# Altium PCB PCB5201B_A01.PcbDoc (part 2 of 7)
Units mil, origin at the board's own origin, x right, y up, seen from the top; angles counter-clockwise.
Board outline 4527.56 x 2362.2 mil, 6 copper layers (Top Layer, GND Layer 2, Signal Layer 3, Signal Layer 4, VCC Layer 5, Bottom Layer), stack 61.221 mil thick; 361 components, 250 nets, 1223 pads, 1068 vias.
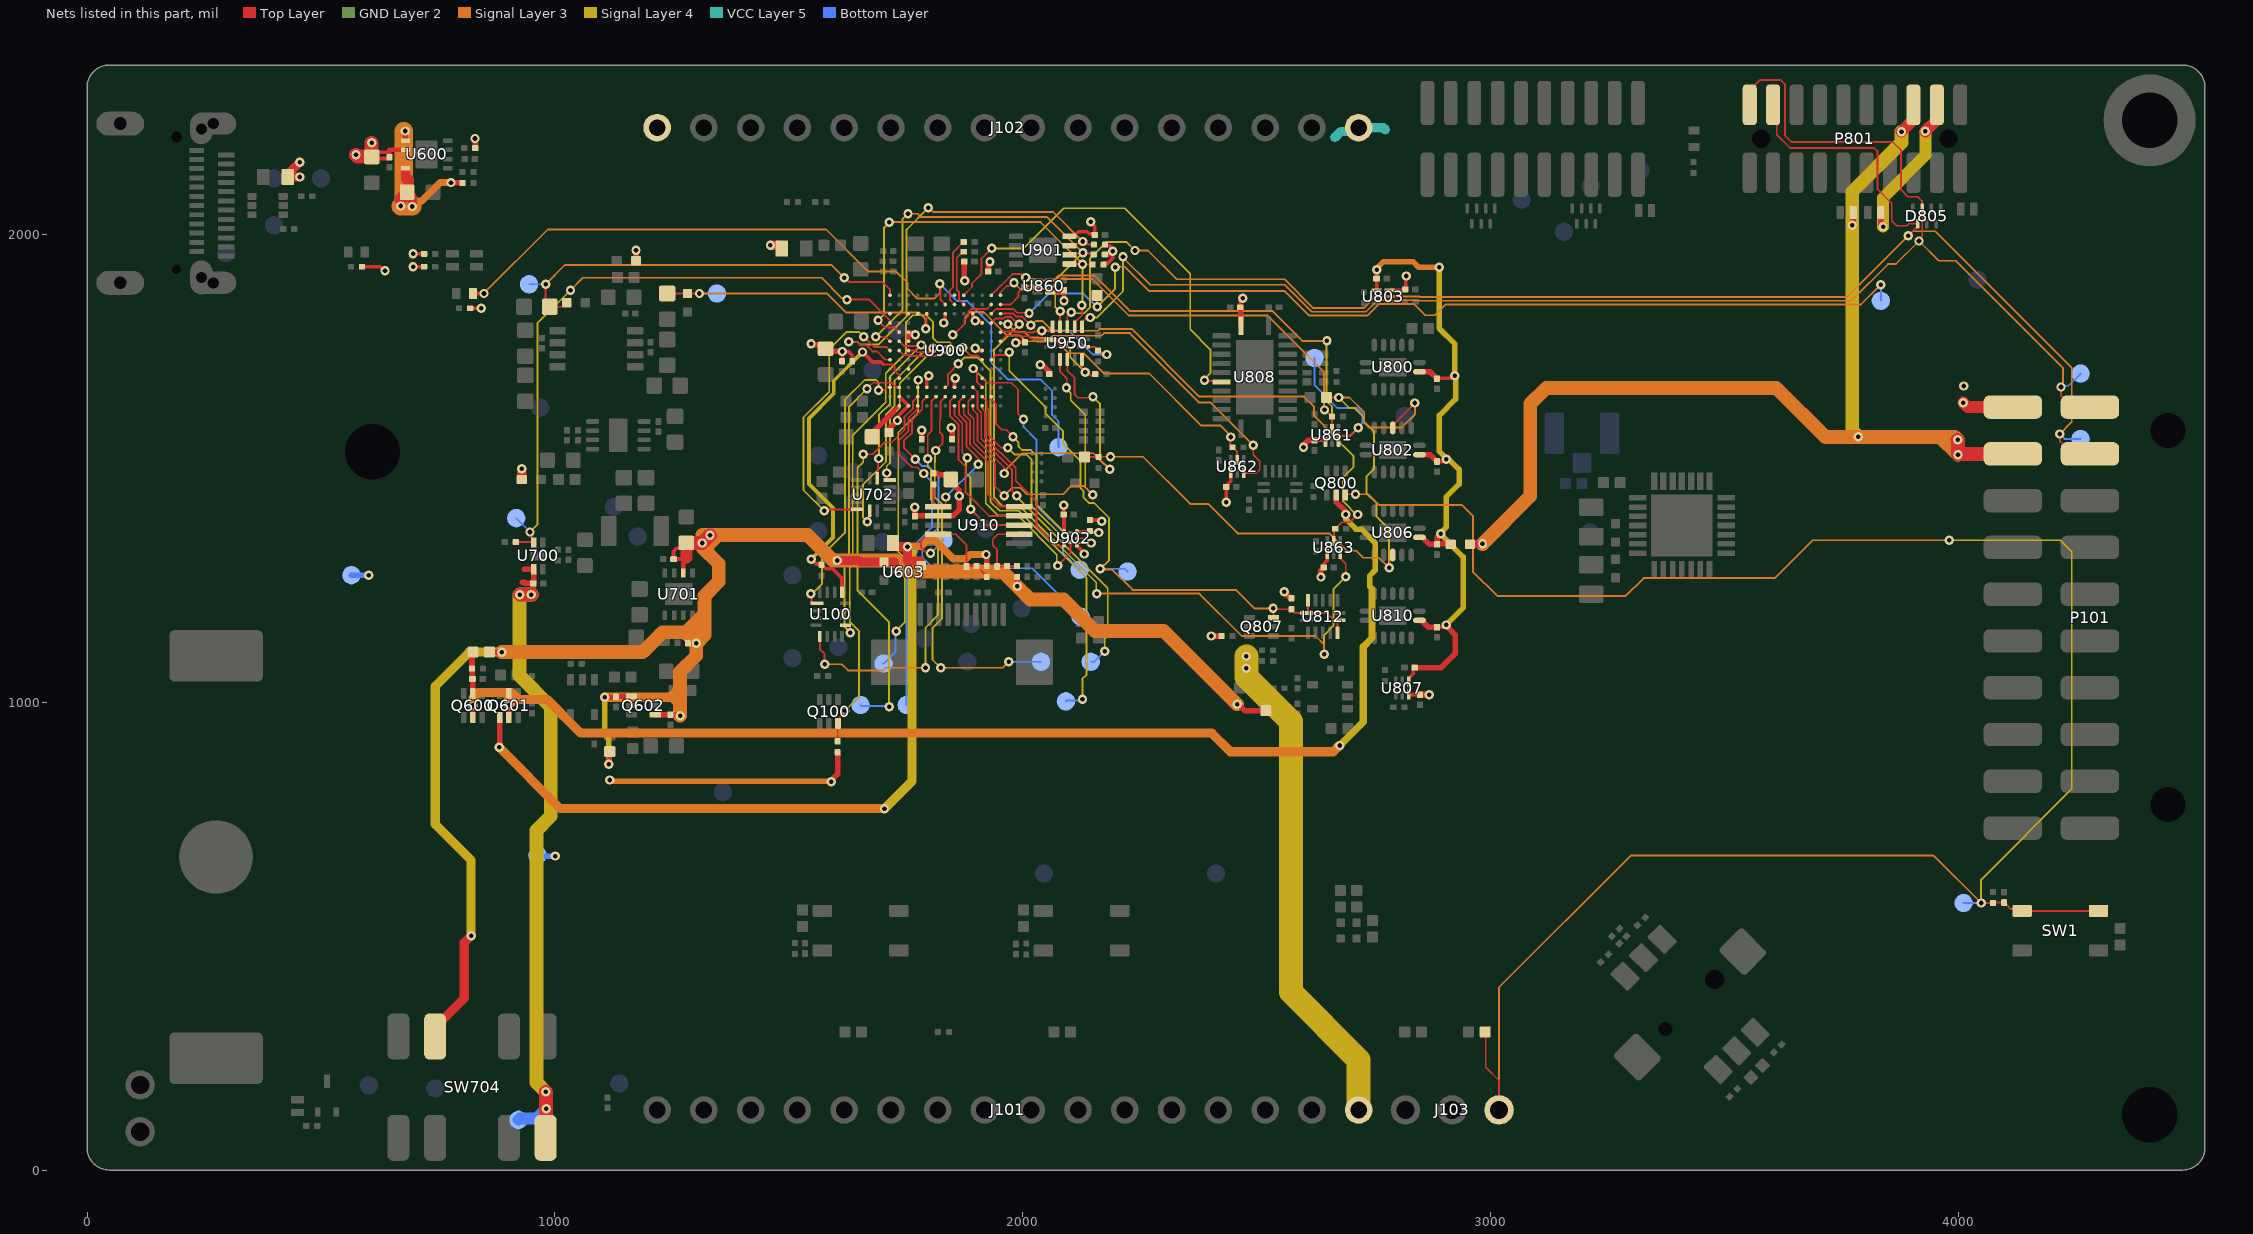
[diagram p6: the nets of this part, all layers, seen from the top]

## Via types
v1: diameter 20, hole 9.84, Top Layer to Bottom Layer, tented both sides, 1068 vias

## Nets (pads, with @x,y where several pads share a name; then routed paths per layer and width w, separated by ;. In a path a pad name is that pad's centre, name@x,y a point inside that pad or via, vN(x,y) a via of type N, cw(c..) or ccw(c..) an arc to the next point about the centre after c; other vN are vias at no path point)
3V3: C607.1 C807.1 C808.1 C860.1 C862.1 C864.1 C866.1 C868.1 C907.1 C908.1 C909.1 C910.1 C911.1 C914.1 C921.1 C922.1 C924.1 C925.1 C926.1 C927.1 C951.1 D807.1 J101.16 J102.16 L704.1 L900.1 P101.20 P801.3 R142.2 R601.2 R838.2 R840.2 R903.1 R906.2 R907.1 R908.1 R909.1 R912.1 R919.1 R920.1 R982.1 TPJ600.1 TPJ950.1 U600.1 U600.4 U803.6 U807.6 U808.1 U860.1 U861.1 U862.1 U863.1 U900.C6 U900.C9 U900.G3 U900.H11 U900.J11 U900.K3 U900.L4 U900.L7 U901.8 U902.A1 U902.E3 U910.2 | length 4365.6
  Top Layer w7.87: R903.1@587.6,1931.1 626.14,1931.1 634.99,1922.24 v1(636.81,1922.24) ; U600.1@680.4,2200.69 680.4,2206.59 ; v1(696.85,1931.1) R919.1@720.47,1931.1 ; v1(696.85,1958.66) R920.1@720.47,1958.66 ; R912.1@818.9,1842.52 v1(842.52,1842.52) ; C924.1@1614.17,1729.33 1614.17,1745.08 1619.09,1750 1627.95,1750 1635.83,1742.13 C925.1@1635.83,1729.33 ; U900.H11@1755.91,1771.65 U900.J11@1755.91,1791.34 1763.78,1791.34 1769.38,1785.74 v1(1770.64,1785.74) ; U900.C9@1795.28,1673.23 1795.28,1693.9 v1(1799.21,1697.83) ; v1(1831.69,1811.02) 1832.68,1811.02 1834.65,1812.99 U900.L7@1834.65,1830.71 ; U900.C6@1854.33,1673.23 1854.33,1689.96 v1@1857.28,1692.91 ; U900.L4@1893.7,1830.71 1893.7,1824.8 1899.61,1818.9 1899.61,1816.93 v1(1898.62,1815.94) 1908.47,1815.94 U900.K3@1913.39,1811.02 ; v1(1898.62,1756.89) 1903.54,1751.97 U900.G3@1913.39,1751.97 ; v1(1985.24,1768.7) 1986.22,1769.69 C911.1@2004.92,1769.69 ; U860.1@2059.06,1875.98 2083.66,1875.98 C862.1@2088.58,1880.91 2088.58,1858.43 v1(2088.48,1858.33) ; v1@2082.68,1421.26 2087.6,1416.34 C914.1@2087.6,1401.57 2088.58,1400.59 U902.A1@2088.58,1366.14 ; U901.8@2105.32,1996.06 2109.04,1996.06 2118.88,2005.91 2137.8,2005.91 2142.19,2001.51 2152.06,2001.51 C951.1@2154.42,1999.15 2154.42,2017.26 2147.64,2024.04 v1@2147.64,2025 ; U902.E3@2116.14,1334.65 2116.14,1334.54 2131.71,1318.97 v1(2131.71,1317.11) ; R906.2@2143.7,1389.76 2166.34,1389.76 v1(2169.29,1386.81) ; v1(2145.59,2027.65) 2145.59,2027.05 v1@2147.64,2025 ; v1@2147.64,2026.57 v1@2147.64,2025 ; v1@2150.59,2022.05 v1@2147.64,2025 ; R908.1@2170.84,1936.02 2172.92,1938.11 2181.22,1938.11 2192.75,1949.64 2192.75,1964.4 v1(2192.91,1964.57) ; R909.1@2175.2,1977.36 2176.55,1976.01 2186.24,1976.01 2193.9,1968.35 v1@2193.9,1964.57 ; v1(2435.67,1427.3) 2435.35,1427.62 2435.35,1460.32 C860.1@2435.04,1460.63 2435.04,1462.6 2444.88,1472.44 U862.1@2444.88,1490.16 ; C808.1@2465.55,1844.49 2465.55,1859.25 v1(2470.47,1864.17) ; C864.1@2624.02,1560.04 2644.69,1560.04 U861.1@2647.64,1557.09 ; C866.1@2643.7,1288.39 2643.7,1296.26 2651.58,1304.13 U863.1@2651.58,1316.93 ; U803.6@2784.45,1880.91 2814.76,1880.91 2814.96,1881.1 C807.1@2814.96,1882.87 ; C807.1@2817.91,1882.87 2818.9,1883.86 2818.9,1910.43 v1(2819.88,1911.42) ; U807.6@2825.31,1016.73 2825.31,1016.52 2847.22,1016.52 C868.1@2847.44,1016.73
  Top Layer w9.84: 680.4,2135.73 U600.4@680.4,2141.63
  Top Layer w11.81: 680.4,2206.59 v1(680.4,2221.36) ; v1(777.84,2111.12) 778.34,2110.63 802.06,2110.63 R601.2@802.45,2110.14 R601.2@802.45,2110.14 ; v1(1547.73,1766.35) 1549.3,1764.78 1569.86,1764.78 1584.65,1750 v1(1614.17,1750) v1@1619.09,1750 ; v1(1590.55,830.1) 1590.55,832.32 1604.57,846.34 R142.2@1604.57,893.02 ; v1(1769.69,1417.32) C922.1@1769.69,1397.64 1770.67,1398.62 U910.2@1819.88,1398.62 1851.38,1398.62 1864.17,1411.42 1864.17,1453.74 C921.1@1843.5,1474.41 ; C927.1@1784.45,1562.01 v1(1784.45,1581.69) ; R982.1@1809.2,1489.42 1809.2,1489.03 1809.59,1488.64 1818.45,1488.64 1820.87,1486.22 1836.61,1486.22 C921.1@1846.46,1476.38 ; v1(1847.44,1586.61) 1849.41,1584.65 C926.1@1849.41,1562.01 ; v1@1875.35,1902.21 C910.1@1875.35,1942.24 ; C908.1@1926.18,1921.26 1926.18,1937.99 v1(1930.12,1941.93) ; v1(2037.32,1721.98) 2038.89,1720.42 2043.33,1720.42 2056.09,1707.66 2056.09,1702.14 2056.48,1701.75 C909.1@2057.27,1701.75 ; R907.1@2175.77,1957.7 2176.17,1958.1 2184.23,1958.1 2189.13,1963 v1@2191.53,1963 ; v1(2403.54,1141.73) 2403.62,1141.66 2425.17,1141.66 R838.2@2425.24,1141.59 ; C808.1@2465.55,1844.49 2466.54,1843.5 U808.1@2466.54,1804.92 ; v1(2559.06,1236.22) 2572.83,1222.44 R840.2@2574.8,1222.44 ; v1(2600.39,1545.28) 2600.39,1550.2 2610.24,1560.04 C864.1@2624.02,1560.04 ; v1(2637.8,1267.72) 2637.8,1282.48 C866.1@2643.7,1288.39 ; D807.1@3834.65,2047.24 3834.65,2021.65 v1(3839.57,2016.73) ; L704.1@1173.5,1943.9 v1(1173.5,1966.54) L704.1@1173.5,1943.9
  Top Layer w13.78: C868.1@2849.45,1016.3 2849.65,1016.1 2868.74,1016.1 v1(2869.09,1015.75)
  Top Layer w19.68: v1(670.56,2060.92) 670.62,2060.98 C607.1@670.62,2075.75 ; 680.4,2118.11 680.4,2135.73 ; C607.1@684.34,2089.47 C607.1@684.34,2090.45 ; 688.98,2118.11 688.98,2095.09 C607.1@684.34,2090.45 ; v1(695.17,2059.94) 695.17,2079.63 C607.1@684.34,2090.45 ; v1(1460.86,1977.05) 1460.92,1976.99 1480.91,1976.99 L900.1@1488.75,1969.14
  Top Layer w25: v1(3930.12,2220.47) 3954.53,2244.88 P801.3@3954.53,2277.22 ; v1(4010.83,1640.75) 4020.47,1631.1 P101.20@4116.93,1631.1
  Top Layer w27.56: C607.1@670.62,2075.75 C607.1@684.34,2089.47
  Signal Layer 3 w11.81: 679.13,2095.47 702.76,2071.85 ; v1(695.17,2059.94) 696.73,2061.51 705.21,2061.51 715.55,2071.85 ; v1(1116.99,833.91) 1118.56,832.34 1124.35,832.34 1125.02,831.67 v1@1588.56,831.67
  Signal Layer 3 w15.75: 702.76,2071.85 715.55,2071.85 754.82,2111.12 v1(777.84,2111.12)
  Signal Layer 3 w39.37: v1@670.47,2060.83 671.36,2059.94 v1(695.17,2059.94) ; 676.83,2078.28 v1@676.83,2221.36
  Signal Layer 4 w25: v1(3839.57,2016.73) 3839.57,2078.74 3930.12,2169.29 v1(3930.12,2220.47)
  Signal Layer 4 w51.18: v1(2478.35,1098.43) v1(2478.35,1072.83) 2478.35,1054.13 2573.82,958.66 2573.82,380.24 2718.5,235.55 J101.16@2718.5,128.43
  VCC Layer 5 w20: 2667.68,2207.72 2680.16,2220.2 2710.28,2220.2 J102.16@2718.5,2228.43 ; J102.16@2711.69,2228.43 J102.16@2718.5,2228.43 ; 2775.59,2224.41 2771.57,2228.43 J102.16@2718.5,2228.43
  Bottom Layer w11.81: TPJ600.1@565.09,1271.73 v1(602.36,1271.65) ; TPJ950.1@962.69,673.23 964.66,671.26 v1(1000.98,671.26)
  other v1: 2087.6,1421.26 1864.17,1440.94 4011.81,1676.18 1856.3,1692.91 1875.98,1901.57
3V6_SW: C608.1 L702.1 Q601.1 R639.2 U603.B1 | length 1860.8
  Top Layer w7.87: U603.B1@1753.94,1285.43 1753.94,1302.17
  Top Layer w11.81: v1@881.89,903.54 Q601.1@881.89,967.52 ; v1(1921.84,1316.04) 1922.84,1315.04 1922.84,1291.73 R639.2@1923.23,1291.34
  Top Layer w19.68: L702.1@1723.03,1340.55 1730.91,1332.68 v1(1753.94,1332.68) 1753.94,1302.17 1780.51,1302.17 C608.1@1783.47,1299.21
  Signal Layer 3 w15.75: v1(1753.94,1332.68) 1754.75,1333.49 1783.45,1333.49 1795.43,1345.47 1812.99,1345.47 1851.38,1307.09 1878.94,1307.09 1887.89,1316.04 v1(1921.84,1316.04)
  Signal Layer 3 w19.68: v1(880.91,903.54) 1011.81,772.64 v1(1704.72,772.64)
  Signal Layer 4 w19.68: v1(1704.72,772.64) 1763.78,831.69 1763.78,1322.75 1753.94,1332.59 v1(1753.94,1332.68)
3V6_SW_SENSE: C641.1 R639.1 R640.2 TP923.1 U910.4 | length 292.7
  Top Layer w3.94: v1(1803.15,1318.9) 1795.28,1318.9 1782.48,1331.69 1782.48,1346.46 1795.28,1359.25 U910.4@1819.88,1359.25 1857.28,1359.25 1879.92,1336.61 C641.1@1879.92,1290.35 1880.91,1291.34 R640.2@1901.58,1291.34 1923.23,1269.69 R639.1@1923.23,1267.72
  Bottom Layer w3.94: v1(1803.15,1318.9) TP923.1@1830.71,1346.46
5V: C600.1 C609.1 C611.1 C673.1 C674.1 C702.1 C703.1 C901.1 D806.1 J102.1 L600.2 L700.1 L800.1 P101.18 P801.5 Q602.1 Q602.4 R600.2 R622.2 R633.2 R681.2 R690.2 R700.2 SW704.3 U600.2 U603.A2 U603.B2 U701.2 U900.A11 U900.B12 | length 7093.1
  Top Layer w7.87: C611.1@608.37,2166.32 cw(c612.04,2159.35) C611.1@613.86,2167.01 ; 646.33,2181 646.33,2176.18 ; C702.1@1253.74,1308.32 1253.74,1322.64 1260.29,1329.19 1272.1,1329.19 C703.1@1275.59,1332.68 ; C702.1@1254.27,1306.48 1279.98,1306.48 1278.54,1302.17 1274.61,1298.23 ; R700.2@1284.51,1126.43 1284.73,1126.21 1301.94,1126.21 v1(1302.17,1125.98) ; 1726.38,1300.2 1738.19,1288.39 U603.B2@1738.19,1285.43 1733.27,1285.43 1728.35,1280.51 1728.35,1274.61 1733.27,1269.69 U603.A2@1738.19,1269.69 ; v1(1732.37,1602.43) 1732.37,1610.32 U900.A11@1755.91,1633.86 U900.B12@1736.22,1653.54 ; 646.33,2176.18 646.33,2164.76 643.97,2162.4 612.37,2162.4 C611.1@608.85,2165.92 619.11,2176.18 646.33,2176.18
  Top Layer w9.84: 646.33,2181 U600.2@680.4,2181 ; U701.2@1274.61,1276.57 1274.61,1298.23
  Top Layer w11.81: v1(820.87,500.98) v1@820.93,500.92 ; v1(829.19,2205.4) 829.6,2204.99 829.6,2185.33 R600.2@829.99,2184.94 ; R622.2@860.24,1107.28 v1(886.81,1107.28) ; v1(1106.3,1010.83) 1106.72,1011.25 1130.03,1011.25 C674.1@1130.42,1011.67 ; v1(1115.55,867.81) 1116.43,868.7 1116.43,893.67 R681.2@1117.32,894.55 ; C674.1@1130.42,1011.67 1130.42,1012.4 1130.82,1012.8 Q602.1@1163.39,1012.8 ; Q602.4@1214.57,973.43 C673.1@1247.05,973.43 ; C673.1@1247.05,973.27 1247.44,972.88 1263.97,972.88 1265.55,971.3 v1(1267.77,971.3) ; C901.1@1714.57,1576.77 1714.57,1584.63 v1(1732.37,1602.43) ; v1(1988.19,1248.03) R633.2@1988.19,1267.72 ; v1(2458.53,995.84) 2460.74,995.84 2474.53,982.05 R690.2@2520.52,982.05 ; v1(3773.62,2019.69) 3775.59,2021.65 D806.1@3775.59,2047.24
  Top Layer w15.75: L800.1@2956.66,1337.73 2982.42,1337.73 v1(2983.27,1338.58)
  Top Layer w19.68: L600.2@429.15,2123.09 v1@454.7,2123.06 ; L600.2@429.15,2123.09 432.49,2126.43 432.49,2132.14 v1(454.75,2154.4) ; SW704.3@744.09,285.43 744.09,309.96 757.72,323.59 762.56,323.59 806.1,367.13 806.1,486.22 v1@819.88,500 ; L700.1@929.13,1476.38 v1(929.13,1499.02) ; v1(1603.92,1303.15) 1650.34,1303.15 1653.29,1300.2 C609.1@1703.74,1300.2 1726.38,1300.2
  Top Layer w25: v1(3878.94,2219.49) 3904.53,2245.08 P801.5@3904.53,2277.22
  Top Layer w25.59: 1281.5,1309.06 C703.1@1281.5,1340.43
  Top Layer w29.53: v1(574.8,2170.28) 578.17,2166.91 607.87,2166.91 C611.1@608.27,2166.51 ; v1(608.27,2195.87) C611.1@608.27,2166.51 ; C611.1@608.85,2165.92 C611.1@608.27,2166.51 ; C703.1@1280.92,1341 C703.1@1281.37,1340.55 ; C703.1@1281.5,1340.43 C703.1@1281.37,1340.55 ; v1(1331.69,1357.28) v1(1314.96,1340.55) C703.1@1281.37,1340.55 ; v1@3998.03,1561.02 3999.79,1559.26 v1(3999.79,1529.15) 4001.75,1531.1 P101.18@4116.93,1531.1
  Signal Layer 3 w19.68: v1(1106.3,1010.83) 1246.06,1010.83 ; 1262.8,1029.53 1262.8,1027.56 1246.06,1010.83 ; 1266.73,994.09 1250,1010.83 ; 1267.77,1010.83 1250,1010.83 ; 1246.06,1010.83 1250,1010.83
  Signal Layer 3 w29.53: v1(886.81,1107.28) 1187.99,1107.28 1230.31,1149.61 1278.54,1149.61 ; v1(1267.77,971.3) 1267.77,1010.83 1267.77,1065.01 1302.17,1099.41 v1@1302.17,1123.03 ; 1318.9,1179.13 1318.9,1163.39 1291.83,1136.32 ; 1318.9,1187.99 1280.51,1149.61 1278.54,1149.61 ; v1(1331.69,1357.28) v1@1331.99,1357.58 ; 1361.22,1357.28 1348.43,1357.28 1322.83,1331.69 v1@1314.96,1331.69 ; v1(2458.53,995.84) 2427.55,1026.82 2301.81,1152.56 2154.53,1152.56 2087.32,1219.77 2016.45,1219.77 v1(1988.19,1248.03) 1956.69,1279.53 1752.95,1279.53 1729.33,1303.15 v1(1603.92,1303.15) 1594.49,1303.15 1540.05,1357.58 v1@1331.99,1357.58 ; v1(2983.27,1338.58) 3085.11,1440.43 3085.11,1637.88 3119.48,1672.24 3611.22,1672.24 3716.13,1567.34 3961.6,1567.34 ; v1@3994.09,1565.94 3992.7,1567.34 3961.6,1567.34 ; v1@3999.05,1534.48 v1(3999.05,1561.63) ; v1(3999.79,1529.15) 3961.6,1567.34 ; 1278.54,1149.61 1291.83,1136.32 ; 1291.83,1136.32 v1(1302.17,1125.98) 1302.58,1125.98 1319.88,1143.28 1319.88,1227.36 1350.39,1257.87 1350.39,1296.26 v1@1314.96,1331.69 ; v1@1314.96,1331.69 v1(1314.96,1340.55) 1314.96,1357.58 v1@1331.99,1357.58
  Signal Layer 4 w11.81: v1(1106.3,1010.83) 1106.3,931.1 1115.55,921.85 v1(1115.55,867.81)
  Signal Layer 4 w19.68: v1(820.87,500.98) 820.87,662.4 744.09,739.17 744.09,1034.45 816.93,1107.28 v1(886.81,1107.28)
  Signal Layer 4 w29.53: v1(3786.42,1567.91) 3773.62,1580.71 v1(3773.62,2019.69) 3773.62,2091.54 3878.94,2196.85 v1(3878.94,2219.49)
  other v1: 454.72,2123.03
5V_DH_SW: C803.1 C805.1 C809.1 C827.1 C869.1 C870.1 L800.2 U800.14 U802.14 U803.1 U806.14 U807.1 U810.14 | length 1570.4
  Top Layer w7.87: C869.1@2756.65,1905.63 2756.77,1905.75 2756.77,1924.8 v1(2756.89,1924.92) ; U803.1@2756.89,1880.91 2756.77,1880.91 2756.77,1903.43 C869.1@2756.89,1903.54 ; U807.1@2825.31,1044.29 2825.31,1051.18 2835,1060.87 2835,1071.81 2836.02,1072.83 C870.1@2837.6,1072.83 ; C827.1@2885.83,1160.43 2900.59,1160.43 v1(2905.51,1165.35) ; C805.1@2885.83,1514.76 2900.59,1514.76 v1(2905.51,1519.69) ; C803.1@2886.81,1692.91 2919.29,1692.91 v1(2924.21,1697.83)
  Top Layer w11.81: C870.1@2838.15,1074.17 2895.04,1074.17 2924.92,1104.05 2924.92,1143.98 2909.45,1159.45 v1@2909.45,1166.34 ; U810.14@2848.43,1175.2 2853.35,1175.2 2868.11,1160.43 C827.1@2885.83,1160.43 ; U806.14@2848.43,1352.36 2855.31,1352.36 2870.08,1337.6 C809.1@2885.83,1337.6 2886.22,1337.99 2886.22,1353.2 2893.3,1360.27 v1(2894.12,1360.27) ; U802.14@2848.43,1529.53 2871.06,1529.53 C805.1@2885.83,1514.76 ; U800.14@2848.43,1706.69 2871.06,1706.69 C803.1@2885.83,1691.93 C803.1@2886.81,1692.91 ; C809.1@2886.22,1338.58 2914.48,1338.58 L800.2@2915.33,1337.73
  Signal Layer 3 w11.81: v1(2756.89,1924.92) 2756.89,1927.13 2762.09,1932.33 2762.09,1932.96 2771.06,1941.93 2834.65,1941.93 2846.46,1930.12 v1(2890.75,1930.12)
  Signal Layer 4 w11.81: v1(2890.75,1930.12) 2890.75,1799.21 2924.21,1765.75 v1(2924.21,1697.83) 2925.78,1696.27 2925.78,1690.48 2925.9,1690.36 2925.9,1648.34 2891.03,1613.47 2891.03,1536.39 2905.51,1521.9 v1(2905.51,1519.69) ; v1(2905.51,1165.35) 2941.93,1201.77 2941.93,1311.02 2894.12,1358.83 2894.12,1362.49 2905.51,1373.88 2905.51,1438.98 2933.07,1466.54 2933.07,1498.03 v1@2908.46,1522.64
5V_SENSE: C635.1 R633.1 R634.2 U910.7 | length 166.9
  Top Layer w3.94: R633.1@1988.19,1291.34 R634.2@1966.54,1291.34 1965.55,1290.35 C635.1@1944.88,1290.35 1944.88,1326.77 1936.3,1335.35 1936.3,1348.93 1946.63,1359.25 U910.7@1993.11,1359.25
5V_SW: C610.1 Q600.2 Q600.5 Q601.2 Q601.5 Q800.5 R622.1 R623.2 | length 2790.4
  Top Layer w11.81: C610.1@823.82,1050.2 823.82,1070.87 R623.2@822.84,1071.85 822.84,1105.32 R622.1@824.8,1107.28 ; Q600.2@824.8,967.52 v1(824.8,993.11) 824.8,994.09 Q600.5@824.8,1018.7 C610.1@824.8,1049.21 ; Q601.2@901.58,967.52 v1(901.57,994.09) Q601.5@901.58,1018.7 ; Q800.5@2670.28,1442.91 2670.28,1428.15 2690.94,1407.48 v1(2690.94,1401.57)
  Signal Layer 3 w19.68: v1(824.8,993.11) 824.8,1008.89 836.59,1020.67 892.72,1020.67 901.57,1011.81 v1(901.57,994.09) 913.39,1005.91 923.23,1005.91 ; 894.68,1020.67 901.57,1020.67 908.46,1020.67 918.31,1010.83 923.23,1005.91 ; v1(2677.63,907.56) 2664.13,894.06 2444.52,894.06 2404.53,934.06 1055.12,934.06 983.27,1005.91 923.23,1005.91
  Signal Layer 4 w11.81: v1(2690.94,1401.57) 2690.94,1391.73 2712.6,1370.08 2724.41,1370.08 2753.94,1340.55 2753.94,1282.48 2741.85,1270.39 2741.85,1247.33 2747.05,1242.13
  Signal Layer 4 w15.75: v1(2677.63,907.56) 2728.63,958.56 2728.63,1119.09 2747.05,1137.51 2747.05,1242.13
#RESET: R805.2 R809.1 R810.2 U802.4 U806.11 | length 1546.8
  Top Layer w3.94: R810.2@2131.89,1524.61 R809.1@2162.4,1524.61 2162.89,1525.1 v1(2187.99,1525.1) ; R805.2@2649.61,1651.57 v1(2676.18,1651.57) ; v1(2783.46,1287.4) 2785.36,1289.3 2785.36,1300.12 2791.34,1306.1 U806.11@2791.34,1314.96 ; U802.4@2791.34,1586.61 2791.34,1592.52 v1(2838.58,1639.76)
  Signal Layer 3 w3.94: v1(2187.99,1525.1) 2257.38,1525.1 2358.27,1424.21 2396.65,1424.21 2459.65,1361.22 2655.51,1361.22 2692.63,1324.1 2713.3,1324.1 2728.35,1309.06 2761.81,1309.06 v1(2783.46,1287.4) ; v1(2676.18,1651.57) 2698.82,1651.57 2730.32,1620.08 2730.32,1597.44 2740.16,1587.6 2811.02,1587.6 2838.58,1615.16 v1(2838.58,1639.76)
  Signal Layer 4 w3.94: v1(2676.18,1651.57) 2698.82,1628.94 2709.65,1628.94 2729.33,1609.25 2729.33,1601.38 2750.98,1579.72 2750.98,1498.03 2734.96,1482 2734.96,1447.13 2756.89,1425.2 2756.89,1396.65 2783.46,1370.08 v1(2783.46,1287.4)
AEM_5V_#ENABLE: U900.L10
AEM_CALIBRATE0: U702.13 U900.G11 | length 527.1
  Top Layer w3.94: v1(1668.03,1386.34) 1668.03,1390.68 1671.26,1393.92 1671.26,1407.09 U702.13@1673.23,1409.06 ; U900.G11@1755.91,1751.97 1771.35,1751.97 1774.93,1748.39 1798.12,1748.39 1805.63,1755.91 v1@1809.06,1755.91
  Signal Layer 4 w3.94: v1(1668.03,1386.34) 1668.03,1386.45 1658.46,1396.01 1658.46,1465.11 1708.18,1514.82 1708.18,1615.66 1726.38,1633.86 1726.38,1687.99 1786.42,1748.03 1798.46,1748.03 1807.69,1757.26 v1(1808.46,1757.26)
AEM_CALIBRATE1: U702.5 U900.G12 | length 468.6
  Top Layer w3.94: v1(1709.65,1490.16) 1709.65,1477.36 1711.61,1475.39 U702.5@1715.95,1475.39 ; U900.G12@1736.22,1751.97 1746.06,1742.13 1759.98,1742.13 1761.88,1740.23 1823.89,1740.23 v1(1837.6,1753.94)
  GND Layer 2 w3.94: v1(1709.65,1490.16) v1@1711.95,1492.46
  Signal Layer 4 w3.94: v1(1709.65,1490.16) 1709.65,1505.15 1716.54,1512.04 1716.54,1609.25 1737.2,1629.92 1737.2,1682.09 1795,1739.88 1823.54,1739.88 v1(1837.6,1753.94)
AEM_CALIBRATE2: U702.6 U900.H12 | length 376.6
  Top Layer w3.94: U702.6@1688.98,1478.74 1690.84,1480.61 1690.84,1519.36 v1(1692.71,1521.23) ; U900.H12@1736.22,1771.65 1746.06,1761.81 1781.51,1761.81 v1(1783.56,1763.86)
  Signal Layer 4 w3.94: v1(1692.71,1521.23) 1692.71,1614.28 1716.54,1638.1 1716.54,1696.84 v1(1783.56,1763.86)
AEM_CALIBRATE3: U702.12 U900.G13 | length 619.7
  Top Layer w3.94: v1(1575.76,1409.42) 1578.74,1412.4 U702.12@1646.26,1412.4 ; v1(1660.43,1781.5) 1682.09,1759.84 1708.66,1759.84 U900.G13@1716.54,1751.97
  Signal Layer 4 w3.94: v1(1575.76,1409.42) 1575.76,1409.48 1531.5,1453.74 1531.5,1608.95 1586.61,1664.07 1586.61,1754.92 1623.03,1791.34 1650.59,1791.34 v1(1660.43,1781.5)
AEM_CURRENT_HIGH_GAIN: C720.1 R764.2 TP706.1 U900.N13 | length 914.6
  Top Layer w3.94: v1(980.31,1893.7) 980.31,1854.33 R764.2@989.17,1845.47 1016.73,1845.47 C720.1@1025.59,1854.33 ; v1(1618.78,1907.3) 1620.45,1907.3 1629.12,1898.62 1699.8,1898.62 1716.54,1881.89 U900.N13@1716.54,1870.08
  Signal Layer 3 w3.94: v1(980.31,1893.7) 1021.7,1935.08 1591,1935.08 v1(1618.78,1907.3)
  Bottom Layer w3.94: TP706.1@944.88,1893.7 v1(980.31,1893.7)
AEM_CURRENT_LOW_GAIN: C724.1 R768.2 TP707.1 U900.L9 | length 665.8
  Top Layer w3.94: R768.2@1240.16,1874.02 C724.1@1283.46,1874.02 v1(1309.06,1874.02) ; v1(1792.54,1798.7) 1794.52,1800.69 1794.52,1829.96 U900.L9@1795.28,1830.71
  Signal Layer 3 w3.94: v1(1309.06,1874.02) 1581.69,1874.02 1622.05,1833.66 1658.46,1833.66 1777.56,1833.66 1792.54,1818.68 v1(1792.54,1798.7)
  Bottom Layer w3.94: v1(1309.06,1874.02) TP707.1@1346.46,1874.02
AEM_SENSE_SELECT: U900.L13
AEM_SWITCH_POS: U900.L11
AEM_VMCU: C708.1 SW704.5 TP709.1 U700.1 | length 1505.4
  Top Layer w11.81: 930.12,1256.89 935.04,1256.89 937.01,1254.92 939.02,1254.92 939.61,1254.33 953.35,1254.33 C708.1@953.74,1253.94 ; 934.06,1284.45 U700.1@954.72,1284.45 954.72,1254.33 954.33,1253.94 C708.1@953.74,1253.94 ; v1(949.8,1230.32) 949.8,1232.53 953.74,1236.47 C708.1@953.74,1253.94
  Top Layer w29.53: v1(924.83,1229.91) 949.4,1229.91 v1(949.8,1230.32) ; SW704.5@980.32,68.9 981.3,69.88 981.3,166.34 v1(980.32,167.32)
  Signal Layer 4 w29.53: v1(949.8,1230.32) 947.83,1230.32 925.24,1230.32 v1(924.83,1229.91) 924.21,1229.29 924.21,1194.88 924.21,1057.09 991.14,990.16 991.14,756.54 960.63,726.03 960.63,187.01 v1(980.32,167.32) 980.32,131.89 v1(981.3,130.91)
  Bottom Layer w25: TP709.1@922.24,107.28 924.99,110.03 960.43,110.03 v1(981.3,130.91) 980.32,131.89 v1(980.32,167.32)
AEM_VMCU_ENABLE: R763.2 TP715.1 U700.4 U900.K13 | length 1396.3
  Top Layer w3.94: R763.2@916.5,1342.43 953.83,1342.43 U700.4@954.72,1341.54 954.72,1346.46 949.92,1351.26 949.92,1361.1 v1(946.85,1364.17) ; v1(1624.6,1860.9) 1672.43,1860.9 1716.4,1816.93 1716.4,1811.16 U900.K13@1716.54,1811.02
  Signal Layer 3 w3.94: v1(1033.46,1880.91) 1060.04,1907.48 1570.22,1907.48 1613.73,1863.97 1621.52,1863.97 v1(1624.6,1860.9)
  Signal Layer 4 w3.94: v1(946.85,1364.17) 962.6,1379.92 962.6,1810.04 v1(1033.46,1880.91)
  Bottom Layer w3.94: TP715.1@917.32,1393.7 v1(946.85,1364.17)
BC_ADC_SPI_CIPO: U900.B6 U910.9 | length 358.6
  Top Layer w3.94: U900.B6@1854.33,1653.54 1844.49,1643.7 1844.49,1612.26 1863.19,1593.56 1863.19,1518.7 1877.95,1503.94 1877.95,1448.82 1928.15,1398.62 U910.9@1993.11,1398.62
BC_ADC_SPI_COPI: U900.A6 U910.8 | length 348.3
  Top Layer w3.94: U900.A6@1854.33,1633.86 1854.33,1613.56 1871.06,1596.82 1871.06,1533.46 v1(1881.89,1522.64) ; v1(1888.78,1412.4) 1922.24,1378.94 U910.8@1993.11,1378.94
  Signal Layer 4 w3.94: v1@1878.94,1515.75 1878.94,1490.16 1888.78,1480.32 v1(1888.78,1412.4)
BC_ADC_SPI_CS: R982.2 U900.B5 U910.1 | length 352.1
  Top Layer w3.94: R982.2@1809.2,1465.8 1809.2,1422.24 1813.14,1418.31 U910.1@1819.88,1418.31 1831.69,1418.31 1835.63,1422.24 v1(1835.63,1438.98) ; U900.B5@1874.02,1653.54 1864.17,1643.7 1864.17,1614.85 1879.92,1599.1 1879.92,1547.24 1905.51,1521.65 v1(1905.51,1508.86)
  Bottom Layer w3.94: v1(1835.63,1438.98) 1901.57,1504.92 v1@1901.57,1507.87
BC_ADC_SPI_SCLK: U900.A5 U910.10 | length 289.1
  Top Layer w3.94: U900.A5@1874.02,1633.86 1874.02,1616.14 1887.8,1602.36 1887.8,1551.18 1926.18,1512.8 1926.18,1443.9 1951.77,1418.31 U910.10@1993.11,1418.31
BC_BUTTON_ENABLE: R981.1 U900.H1 U950.6 U950.12 | length 285.6
  Top Layer w3.94: U900.H1@1952.76,1771.65 1965.83,1784.73 1991.08,1784.73 1993.14,1782.68 2014.57,1782.68 2021.65,1775.59 U950.6@2060.63,1775.59 2087.55,1775.59 2098.58,1764.56 v1(2101.8,1764.56) ; U950.12@2126.97,1732.87 2126.97,1714.37 2133.86,1707.47 v1(2133.86,1705.56) ; v1@2134.79,1706.55 2134.85,1706.55 2136.99,1706.55 2145.19,1698.35 R981.1@2151.7,1698.35
  Signal Layer 4 w3.94: v1(2101.8,1764.56) 2101.8,1737.63 v1(2133.86,1705.56)
BC_DAC_OUT: U900.N6
BC_DBG_#RESET: LED903.1 TPJ956.1 U900.M7 | length 1704.8
  Top Layer w3.94: v1(1822.84,1894.69) 1824.8,1892.72 1824.8,1860.24 U900.M7@1834.65,1850.39
  Top Layer w7.87: LED903.1@824.8,1874.02 v1(848.43,1874.02)
  Signal Layer 3 w3.94: v1(848.43,1874.02) 985.24,2010.83 1579.72,2010.83 1669.68,1920.87 1729.72,1920.87 1753.94,1896.65 1753.94,1883.86 1774.61,1863.19 1811.02,1863.19 1822.84,1875 v1(1822.84,1894.69)
  Bottom Layer w3.94: v1(1822.84,1894.69) 1859.25,1858.27 1880.91,1858.27 1933.07,1806.1 1933.07,1726.38 1969.49,1689.96 2038.52,1689.96 2062.99,1665.49 2062.99,1614.17 2076.89,1600.28 TPJ956.1@2076.89,1545.33
BC_DBG_TCK_SWCLK: TPJ954.1 U900.C10 | length 668.4
  Top Layer w3.94: U900.C10@1775.59,1673.23 1775.59,1684.06 1773.62,1686.02 1773.62,1687.01 1775.59,1688.98 v1(1776.58,1688.98) ; v1@1780.51,1687.08 v1@1780.51,1688.98
  Signal Layer 4 w3.94: v1(1730.04,1151.57) 1730.04,1153.26 1748.03,1171.26 1748.03,1308.07 1734.25,1321.85 1734.25,1576.77 1776.58,1619.1 v1(1776.58,1688.98)
  Bottom Layer w3.94: TPJ954.1@1702.89,1082.73 1728.35,1108.19 1728.35,1149.89 v1(1730.04,1151.57)
BC_DBG_TDO_SWO: TPJ955.1 U900.A10 | length 714.4
  Top Layer w3.94: U900.A10@1775.59,1633.86 1775.59,1627.64 1755.71,1607.77 1755.71,1579.9 1736.22,1560.41 1736.22,1529.35 1763.12,1502.45 1775.11,1502.45 v1(1788.39,1489.17)
  Bottom Layer w3.94: TPJ955.1@1752.09,994.13 1752.09,1299.33 1774.61,1321.85 1774.61,1342.52 1806.1,1374.02 1806.1,1471.46 v1(1788.39,1489.17)
BC_DBG_TMS_SWDIO: TPJ953.1 U900.B10 | length 827.8
  Top Layer w3.94: v1(1659.18,1530.4) 1680,1530.4 1705.71,1556.1 1720.78,1556.1 1747.84,1583.16 1747.84,1611.03 1765.75,1628.94 1765.75,1643.7 U900.B10@1775.59,1653.54
  Signal Layer 4 w3.94: v1(1659.18,1530.4) 1659.18,1513.51 1646.65,1500.98 1646.65,1239.17 1714.57,1171.26 v1(1714.57,990.7)
  Bottom Layer w3.94: TPJ953.1@1653.59,994.13 1655.3,992.42 1712.85,992.42 v1(1714.57,990.7)
BC_DISP_AVAILABLE: Q100.6 R142.1 U900.F3 | length 1201.3
  Top Layer w3.94: R142.1@1604.57,916.64 1604.94,917.01 1604.94,953.95 Q100.6@1605.31,954.32 1605.31,960.23 1609.83,964.75 1609.83,969.59 1620.32,980.08 v1(1620.32,981.59) ; v1(1872.05,1757.87) 1888.78,1741.14 1904.53,1741.14 U900.F3@1913.39,1732.28
  Signal Layer 4 w3.94: v1(1620.32,981.59) 1650.54,1011.81 1650.54,1151.84 1630.39,1171.99 1630.39,1288.06 1636.81,1294.48 1636.81,1570.87 1707.4,1641.45 1707.4,1703.46 1750.98,1747.05 1750.98,1812.99 1765.47,1827.48 1793.85,1827.48 1808.07,1813.26 1808.07,1779.53 1817.85,1769.75 1843.67,1769.75 1855.54,1757.87 v1(1872.05,1757.87)
BC_DISP_COM: U900.E11
BC_DISP_PWR_ENABLE: R140.2 U100.13 U900.D12 | length 754.9
  Top Layer w3.94: R140.2@1570.4,1293.91 R140.2@1570.4,1294.31 ; 1700.2,1722.44 1701.77,1722.44 1721.01,1722.44 1726.38,1717.07 1726.38,1716.68 1726.38,1708.52 1736.22,1698.68 U900.D12@1736.22,1692.91
  Top Layer w7.87: v1(1548.23,1306.1) 1548.64,1306.1 1558.9,1295.84 1568.87,1295.84 R140.2@1570.4,1294.31 ; R140.2@1570.4,1293.91 1572.76,1291.55 1573.16,1291.55 1579.28,1285.43 1593.5,1285.43 1613.78,1265.16 U100.13@1613.78,1235.24 ; v1(1657.7,1748.88) 1679.22,1727.36 1696.85,1727.36 1701.77,1722.44
  Signal Layer 4 w7.87: v1(1548.23,1306.1) 1594.49,1352.36 1594.49,1415.35 1543.31,1466.54 1543.31,1606.85 1596.46,1660 1596.46,1687.64 v1(1657.7,1748.88)
BC_DISP_SPI_COPI: U100.5 U900.B8 | length 894
  Top Layer w3.94: U100.5@1566.54,1140.75 1566.54,1113.59 1576.77,1103.35 1576.77,1081.68 v1(1576.71,1081.62) ; v1(1797.24,1520.67) 1797.24,1571.85 1805.12,1579.72 1805.12,1643.7 U900.B8@1814.96,1653.54
  Signal Layer 3 w3.94: v1(1576.71,1081.62) 1576.86,1081.47 1613.41,1081.47 1626.97,1067.91 1701.77,1067.91 1707.68,1073.82 v1@1792.14,1073.82
  Signal Layer 4 w3.94: v1(1792.32,1073.82) 1792.32,1159.45 1818.9,1186.02 1818.9,1418.31 1804.13,1433.07 1804.13,1497.05 1797.24,1503.94 v1(1797.24,1520.67)
BC_DISP_SPI_CS: U100.9 U900.C12 | length 648.7
  Top Layer w3.94: U100.9@1621.65,1164.37 1629.21,1164.37 1631.18,1162.4 1631.18,1149.32 v1(1631.65,1148.85) ; v1(1667.32,1670.28) 1680.12,1683.07 1720.61,1683.07 1730.46,1673.23 U900.C12@1736.22,1673.23
  Signal Layer 4 w3.94: v1(1631.65,1148.85) 1619.39,1161.12 1619.39,1293.6 1628.94,1303.15 1628.94,1631.89 v1(1667.32,1670.28)
BC_DISP_SPI_SCLK: U100.1 U900.C13 | length 613.2
  Top Layer w3.94: v1(1547.38,1231.74) 1548.82,1230.3 1548.82,1213.58 1550.79,1211.61 U100.1@1560.63,1211.61 ; v1(1691.93,1667.32) 1703.74,1667.32 1709.65,1673.23 U900.C13@1716.54,1673.23
  Signal Layer 4 w3.94: v1(1547.38,1231.74) 1550.26,1231.74 1570.87,1252.34 1570.87,1312.99 1620.08,1362.2 1620.08,1646.43 1662.62,1688.98 1687.01,1688.98 1691.93,1684.06 v1(1691.93,1667.32)
BC_I2C_EXP_ENABLE: R950.1 U900.J1 U950.5 U950.13 | length 337.5
  Top Layer w3.94: U900.J1@1952.76,1791.34 1952.76,1792.6 1994.35,1792.6 1996.4,1790.55 2023.4,1790.55 2025.37,1792.52 2038.69,1792.52 v1(2040.74,1794.57) ; v1@2041.28,1795.21 2062.01,1795.21 2063.98,1797.18 U950.5@2063.98,1802.56 ; U950.13@2130.32,1759.84 2153.94,1759.84 2161.42,1752.36 2161.42,1751.85 2165.75,1747.52 2171.57,1747.52 2175.51,1743.59 v1(2179.86,1743.59)
  Bottom Layer w3.94: v1(2040.74,1794.57) 2099.13,1794.57 2150.11,1743.59 v1(2179.86,1743.59)
BC_I2C_EXP_SCL: D805.5 P101.17 P801.17 TPJ651.1 U950.3 | length 3393.4
  Top Layer w3.94: U950.3@2095.47,1802.56 2095.47,1824.8 v1(2104.33,1833.66) ; P801.17@3604.53,2277.22 3612.2,2269.55 3612.2,2213.58 3640.75,2185.04 3820.87,2185.04 3827.76,2178.15 3827.76,2096.54 3855.4,2068.9 3855.96,2068.9 3858.27,2066.59 3858.27,2029.53 3869.09,2018.7 3889.76,2018.7 3894.09,2023.03 D805.5@3913.39,2023.03 3913.39,2017.72 v1(3893.39,1997.73) ; v1(4217.07,1573.52) 4217.88,1572.71 4217.88,1557.62 4244.39,1531.1 P101.17@4281.89,1531.1
  Signal Layer 3 w3.94: v1(2240.24,1965.83) 2267.82,1965.83 2329.13,1904.53 2560.04,1904.53 2621.77,1842.8 2729.61,1842.8 2754.36,1867.55 2848.98,1867.55 2850.29,1866.24 3761.91,1866.24 v1(3893.39,1997.73) 3894.3,1997.73 3903.46,2006.89 3951.37,2006.89 4243.11,1715.15 4243.11,1599.56 v1(4217.07,1573.52)
  Signal Layer 4 w3.94: v1(2104.33,1833.66) 2106.3,1831.69 2131.68,1831.69 2143.7,1843.71 2143.7,1947.83 2180.12,1984.25 2221.84,1984.25 v1@2240.24,1965.86
  Bottom Layer w3.94: v1(4217.07,1573.52) 4227.62,1562.98 TPJ651.1@4261.81,1562.98
BC_I2C_EXP_SDA: D805.3 P101.19 P801.19 TPJ650.1 U950.1 | length 3333.3
  Top Layer w3.94: U950.1@2126.97,1802.56 2126.97,1812.01 2134.43,1819.47 2141.33,1819.47 v1(2144.4,1822.54) ; P801.19@3554.53,2277.22 3554.53,2308.47 3576.77,2330.71 3620.28,2330.71 3629.92,2321.07 3629.92,2211.61 3643.7,2197.83 3860.24,2197.83 3877.95,2180.12 3877.95,2095.47 3892.72,2080.71 3913.39,2080.71 3922.43,2071.67 D805.3@3922.43,2061.21 ; v1(3916.34,1986.22) 3916.34,1989.67 3923.23,1996.56 D805.3@3923.23,2055.71 ; v1(4220.05,1674.12) 4220.05,1655.44 4244.39,1631.1 P101.19@4281.89,1631.1
  Signal Layer 3 w3.94: v1(2214.57,1952.76) 2214.57,1950.79 2272.64,1892.72 2560.41,1892.72 2618.2,1834.93 2734.13,1834.93 2758.89,1859.68 2845.71,1859.68 2847.02,1858.37 3771.75,1858.37 3850.39,1937.01 3867.13,1937.01 v1(3916.34,1986.22) 3958.66,1943.9 3995.08,1943.9 4224.41,1714.57 4224.41,1682.82 4220.05,1678.46 v1(4220.05,1674.12)
  Signal Layer 4 w3.94: v1(2144.4,1822.54) 2158.18,1822.54 2176.18,1840.54 2214.57,1878.92 v1(2214.57,1952.76)
  Bottom Layer w3.94: v1(4220.05,1674.12) 4222.75,1676.82 4235.96,1676.82 TPJ650.1@4261.81,1702.68
BC_SPI_CIPO: U900.B3 U902.C3 | length 496.1
  Top Layer w3.94: U900.B3@1913.39,1653.54 1923.23,1643.7 1923.23,1629.78 1927.17,1625.84 1927.17,1570.87 1953.74,1544.29 v1(1968.5,1544.29) ; U902.C3@2116.14,1350.39 2136.81,1350.39 v1(2146.65,1340.55)
  Signal Layer 4 w3.94: v1(1968.5,1544.29) 1983.27,1529.53 2008.86,1529.53 2018.7,1519.69 2018.7,1420.28 2098.43,1340.55 v1(2146.65,1340.55)
BC_SPI_COPI: U900.C3 U902.D2 | length 630.4
  Top Layer w3.94: v1(1894.68,1713.58) 1902.56,1705.71 1902.56,1684.06 U900.C3@1913.39,1673.23 ; v1(2074.8,1292.32) 2102.36,1319.88 U902.D2@2102.36,1342.52
  Signal Layer 4 w3.94: v1(1894.68,1713.58) 1921.26,1687.01 1921.26,1425.2 1946.85,1399.61 1989.17,1399.61 2072.91,1315.87 2072.91,1294.22 v1(2074.8,1292.32)
BC_SPI_CS: R906.1 U900.B2 U902.A3 | length 492.8
  Top Layer w3.94: U900.B2@1933.07,1653.54 1933.07,1647.78 1942.91,1637.94 1942.91,1595.47 1955.71,1582.68 1964.57,1582.68 v1(1979.33,1567.91) ; U902.A3@2116.14,1366.14 R906.1@2143.7,1366.14 2145.34,1364.51 2161.22,1364.51 v1(2162.86,1362.87)
  Signal Layer 4 w3.94: v1(1979.33,1567.91) 1991.14,1556.1 1991.14,1547.24 1999.02,1539.37 2017.72,1539.37 2029.53,1527.56 2029.53,1423.23 2089.88,1362.87 v1(2162.86,1362.87)
BC_SPI_SCLK: U900.A3 U902.E1 | length 381.6
  Top Layer w3.94: U900.A3@1913.39,1633.86 1913.39,1628.49 1919.29,1622.58 1919.29,1566.93 1985.24,1500.98 1985.24,1473.66 2029.53,1429.36 2029.53,1376.97 2071.85,1334.65 U902.E1@2088.58,1334.65
BC_TRACECLK: TPJ957.1 U900.B7 | length 835.9
  Top Layer w3.94: v1(1813.98,1538.39) 1828.46,1552.87 1828.46,1571.82 1822.83,1577.45 1822.83,1603.35 1824.8,1605.32 1824.8,1643.7 U900.B7@1834.65,1653.54
  Signal Layer 3 w3.94: v1(1824.8,1073.82) 1957.9,1073.82 v1(1970.58,1086.5)
  Signal Layer 4 w3.94: v1(1813.98,1538.39) 1812.99,1537.4 1812.99,1514 1812.29,1513.3 1812.29,1438.7 1827.76,1423.23 1827.76,1179.13 1807.09,1158.46 1807.09,1091.54 v1(1824.8,1073.82)
  Bottom Layer w3.94: v1(1970.58,1086.5) 1970.51,1086.58 TPJ957.1@2039.31,1086.58
BC_TRACED0: TPJ958.1 U900.C7 | length 1000.8
  Top Layer w3.94: U900.C7@1834.65,1673.23 1840.55,1679.13 1840.55,1701.77 v1(1862.2,1723.43)
  Signal Layer 4 w3.94: v1(1862.2,1723.43) 1875.98,1737.2 1902.56,1737.2 1931.1,1708.66 1931.1,1429.13 1950.79,1409.45 1992.13,1409.45 2136.81,1264.76 2136.81,1059.06 2127.95,1050.2 v1(2127.95,1006.14)
  Bottom Layer w3.94: TPJ958.1@2092.51,1001.98 2094.6,1004.06 2125.87,1004.06 v1(2127.95,1006.14)
BC_TRACED1: TPJ959.1 U900.C4 | length 725.5
  Top Layer w3.94: U900.C4@1893.7,1673.23 1903.54,1663.39 1903.54,1627.2 1911.42,1619.32 1911.42,1562.99 1977.36,1497.05 1977.36,1451.77 v1(1987.2,1441.93)
  Signal Layer 4 w3.94: v1(1987.2,1441.93) 1987.2,1438.98 2182.09,1244.1 2182.09,1142.72 2175.65,1136.28 v1(2175.65,1109.29)
  Bottom Layer w3.94: TPJ959.1@2145.61,1086.58 2152.94,1086.58 v1(2175.65,1109.29)
BC_TRACED2: TPJ960.1 U900.D3 | length 531
  Top Layer w3.94: U900.D3@1913.39,1692.91 1923.23,1683.07 1976.07,1683.07 1990.16,1668.98 1990.16,1617.13 v1@2004.84,1602.45
  Bottom Layer w3.94: v1(2001.97,1605.32) 2001.97,1588.58 2029.53,1561.02 2029.53,1420.28 2086.61,1363.19 2086.61,1318.78 TPJ960.1@2122.01,1283.38
BC_TRACED3: TPJ961.1 U900.B9 | length 808.7
  Top Layer w3.94: v1@1771.76,1518.81 1746.06,1544.51 1746.06,1559.11 1763.59,1576.64 1763.59,1604.51 1785.43,1626.35 1785.43,1643.7 U900.B9@1795.28,1653.54
  Bottom Layer w3.94: v1(1770.78,1519.8) 1785.66,1504.92 1798.23,1504.92 1819.88,1483.27 1819.88,1373.6 1785.34,1339.06 1785.34,1310.13 1809.06,1286.42 2020.67,1286.42 TPJ961.1@2124.01,1183.08
BC_UIF_BUTTON0: U900.B4 U950.9 | length 782.7
  Top Layer w3.94: U900.B4@1893.7,1653.54 1883.86,1643.7 1883.86,1618.11 1895.67,1606.3 1895.67,1555.12 1940.94,1509.84 1940.94,1461.61 v1(1960.63,1441.93) ; U950.9@2079.72,1732.87 2079.72,1707.68 2094.37,1693.03 2094.37,1673.21 v1(2093.7,1672.53)
  Signal Layer 3 w3.94: v1(1960.63,1441.93) 1977.36,1458.66 1995.08,1458.66 2008.86,1444.88 2086.61,1444.88 2104.33,1462.6 2130.91,1462.6 v1(2149.61,1443.9)
  Signal Layer 4 w3.94: v1(2093.7,1672.53) 2093.7,1669.72 2103.01,1660.41 2103.01,1646 2133.86,1615.16 2133.86,1459.65 v1(2149.61,1443.9)
BC_UIF_BUTTON1: U900.A4 U950.10 | length 730.5
  Top Layer w3.94: U900.A4@1893.7,1633.86 1893.7,1625.9 1903.54,1616.06 1903.54,1559.05 1960.63,1501.97 v1(1960.63,1489.17) ; U950.10@2095.47,1732.87 2095.47,1709.02 2110.99,1693.51 2110.99,1658.32 2118.29,1651.03 2148.08,1651.03 v1(2150.42,1653.38)
  Signal Layer 3 w3.94: v1@1962.6,1485.24 1962.6,1496.06 1999.02,1532.48 2151.57,1532.48 v1(2186.02,1498.03)
  Signal Layer 4 w3.94: v1(2150.42,1653.38) 2165.35,1638.45 2165.35,1518.7 v1(2186.02,1498.03)
BC_VCOM_CTS: U863.3 U900.K2 | length 1579.7
  Top Layer w3.94: U900.K2@1933.07,1811.02 1942.91,1820.87 1959.42,1820.87 1962.1,1823.54 1975.82,1823.54 1993.11,1806.25 v1(1993.11,1808.07) ; v1@1992.13,1804.13 1994.09,1802.17 v1@1995.08,1803.15 ; U863.3@2679.13,1316.93 2679.13,1308.07 2690.94,1296.26 v1(2690.94,1268.7)
  Signal Layer 3 w3.94: v1(2158.46,1232.28) 2377.95,1232.28 2468.5,1141.73 2626.21,1141.73 2644.68,1123.25 v1(2644.68,1102.36)
  Signal Layer 4 w3.94: v1(1993.11,1808.07) 1938.98,1753.94 1938.98,1437.99 1956.69,1420.28 1993.11,1420.28 2157.32,1256.06 2157.32,1233.43 v1(2158.46,1232.28) ; v1(2644.68,1102.36) 2644.68,1143.7 2664.37,1163.39 2664.37,1242.13 v1(2690.94,1268.7)
BC_VCOM_CTS_DIR: R853.2 U863.5 U900.N2 | length 1318.5
  Top Layer w3.94: U900.N2@1933.07,1870.08 1978.35,1915.35 1996.46,1915.35 2003.55,1908.26 v1(2006.8,1908.26) ; U863.5@2665.35,1344.49 2665.35,1368.11 R853.2@2668.31,1371.06 2682.09,1384.84 2699.8,1384.84 v1(2716.54,1401.57)
  Signal Layer 3 w3.94: v1(2006.8,1908.26) 2009.88,1905.19 2022.1,1905.19 2025.59,1901.69 2066.06,1901.69 2077.06,1912.69 2152.67,1912.69 2228.74,1836.61 2533.46,1836.61 2597.44,1772.64 v1(2650.59,1772.64)
  Signal Layer 4 w3.94: v1(2650.59,1772.64) 2649.61,1771.65 2649.61,1644.38 2661.42,1632.57 2661.42,1571.85 2706.41,1526.85 2707.68,1525.59 2707.68,1503.94 2685.04,1481.3 2685.04,1429.36 2716.54,1397.86 v1(2716.54,1401.57)
BC_VCOM_ENABLE: Q807.3 R840.1 TP930.1 U812.5 U812.6 U812.12 U812.13 U900.F2 | length 1305.9
  Top Layer w3.94: U900.F2@1933.07,1732.28 1942.91,1742.13 1960.63,1742.13 1966.54,1748.03 v1(1971.46,1748.03) ; v1(2535.43,1200.79) v1@2536.42,1199.8 ; Q807.3@2541.34,1181.1 Q807.3@2536.42,1181.1 v1@2536.42,1199.8 ; U812.12@2610.24,1217.91 2610.24,1194.29 U812.13@2606.89,1190.94 ; U812.5@2673.23,1148.23 U812.6@2673.23,1175.2 ; U812.6@2676.58,1175.2 U812.6@2673.23,1175.2 ; v1@2536.42,1199.8 2537.4,1198.82 R840.1@2574.8,1198.82 2582.68,1190.94 U812.13@2606.89,1190.94 ; U812.13@2606.89,1190.94 2650.59,1190.94 2666.34,1175.2 U812.6@2673.23,1175.2
  Signal Layer 3 w3.94: v1(2166.05,1285.43) 2167.94,1283.54 2191.85,1283.54 2235.24,1240.16 2455.71,1240.16 2495.08,1200.79 v1(2535.43,1200.79)
  Signal Layer 4 w3.94: v1(1971.46,1748.03) 1971.46,1708.66 2049.21,1630.91 2049.21,1617.13 2086.61,1579.72 2086.61,1553.15 2124.02,1515.75 2124.02,1457.68 2129.92,1451.77 2129.92,1437.99 2141.73,1426.18 2152.56,1426.18 2184.76,1393.98 2184.76,1304.14 v1(2166.05,1285.43)
  Bottom Layer w3.94: v1(2166.05,1285.43) 2218.5,1285.43 TP930.1@2224.41,1279.53
BC_VCOM_RTS: U862.3 U900.K1 | length 752.9
  Top Layer w3.94: U900.K1@1952.76,1811.02 1965.55,1811.02 v1(1968.5,1808.07) ; U862.3@2472.44,1490.16 2499.97,1490.16 2506.94,1497.13 2506.94,1515.53 2493.07,1529.39 v1(2493.07,1549.87)
  Signal Layer 3 w3.94: v1(1968.5,1808.07) 1984.25,1792.32 2003.9,1792.32 2016.45,1779.77 2033.66,1779.77 2034.33,1779.1 2059.61,1779.1 2063.98,1783.46 2168.31,1783.46 2174.21,1789.37 2229.33,1789.37 2377.95,1640.75 2402.2,1640.75 v1(2493.07,1549.87)
BC_VCOM_RTS_DIR: R852.2 U862.5 U900.M2 | length 911.3
  Top Layer w3.94: v1(1850.39,1785.43) 1852.58,1785.43 1875.6,1808.45 1875.6,1816.55 1883.86,1824.8 1883.86,1834.79 1889.62,1840.55 1923.23,1840.55 U900.M2@1933.07,1850.39 ; v1(2445.08,1567.25) 2443.9,1566.07 2443.9,1550.2 R852.2@2448.82,1545.28 2458.66,1535.43 U862.5@2458.66,1517.72
  Signal Layer 3 w3.94: v1(1850.39,1785.43) 1852.58,1785.43 1876.97,1809.82 1876.97,1822.83 1888.78,1834.65 1916.34,1834.65 1966.54,1784.45 1994.09,1784.45 2006.64,1771.9 2030.4,1771.9 2031.07,1771.23 2073.26,1771.23 2098.43,1746.06 2130.88,1746.06 2167.95,1708.98 2173.67,1703.26 2270.16,1703.26 2381.89,1591.54 2423.45,1591.54 2445.08,1569.91 v1(2445.08,1567.25)
BC_VCOM_RXD: R882.2 TPJ606.1 U900.L2 | length 2150.3
  Top Layer w3.94: U900.L2@1933.07,1830.71 1942.91,1840.55 1981.08,1840.55 1988.67,1832.96 2012.52,1832.96 v1(2013.78,1831.69) ; v1(2159.19,1845.42) 2159.19,1869.82 R882.2@2159.45,1870.08
  Signal Layer 3 w3.94: v1(2197.86,1930.09) 2198.87,1931.1 2218.5,1931.1 2269.96,1879.64 2559.57,1879.64 2612.16,1827.05 2737.4,1827.05 2762.15,1851.8 2836.35,1851.8 2860.72,1827.43 2881.56,1827.43 2904.63,1850.49 3792.42,1850.49 v1(3834.65,1892.72)
  Signal Layer 4 w3.94: v1@2159.45,1845.68 2197.86,1884.09 v1(2197.86,1930.09)
  Bottom Layer w3.94: v1(2013.78,1831.69) 2055.96,1873.87 2130.06,1873.87 2158.52,1845.42 v1(2159.19,1845.42) ; TPJ606.1@3834.79,1858.33 v1@3834.79,1892.72
BC_VCOM_RXD_DIR: R850.2 U860.5 U900.M1 | length 101.2
  Top Layer w3.94: U900.M1@1952.76,1850.39 1974.63,1850.39 1990.86,1866.62 1990.86,1876.69 1996.94,1882.77 1999.59,1882.77 2003.93,1887.1 R850.2@2003.93,1887.49 2006.2,1889.76 U860.5@2031.5,1889.76
BC_VCOM_TXD: TPJ607.1 U861.3 U900.L1 | length 1180.3
  Top Layer w3.94: U900.L1@1952.76,1830.71 1953.46,1831.41 1979.08,1831.41 1985.41,1825.08 1998.51,1825.08 2017.49,1806.1 v1(2017.72,1806.1) ; U861.3@2675.2,1557.09 2675.2,1561.99 2683.37,1570.16 2701.07,1570.16 v1(2717.52,1586.61)
  Signal Layer 3 w3.94: v1(2017.72,1806.1) 2019.2,1806.1 2028.05,1814.96 2042.86,1814.96 2063.53,1794.29 2161.42,1794.29 2165.35,1798.23 2233.27,1798.23 2377.95,1653.54 2601.38,1653.54 2623.03,1631.89 2623.03,1612.2 2665.35,1569.88 2700.79,1569.88 v1(2717.52,1586.61)
  Bottom Layer w3.94: TPJ607.1@2624.15,1736.24 2624.15,1678.01 2673.23,1628.94 2715.55,1628.94 2726.38,1618.11 2726.38,1596.95 2717.52,1588.09 v1(2717.52,1586.61)
BC_VCOM_TXD_DIR: R851.2 U861.5 U900.N1 | length 932.4
  Top Layer w3.94: U900.N1@1952.76,1870.08 1952.76,1876.97 1965.73,1889.94 1970.63,1889.94 1977.28,1896.59 v1(1981.63,1896.59) ; v1(2645.39,1625) 2646.74,1625 2661.02,1610.72 R851.2@2661.41,1610.72 U861.5@2661.42,1584.65
  Signal Layer 3 w3.94: v1(1981.63,1896.59) 1994.36,1883.86 2059.36,1883.86 2080.32,1904.81 2149.41,1904.81 2227.45,1826.77 2523.62,1826.77 2644.68,1705.71 2644.68,1625.7 v1(2645.39,1625)
BOARD_ID_SCL: R907.2 U900.H13 U901.6 U950.4 | length 976.2
  Top Layer w3.94: v1(1686.02,1781.5) 1706.69,1781.5 U900.H13@1716.54,1771.65 ; U950.4@2079.72,1802.56 2079.94,1802.77 2079.94,1835.5 v1(2080.15,1835.71) ; U901.6@2100.18,1956.69 2102.39,1958.91 2126.73,1958.91 v1(2128.94,1961.12) ; v1@2129.92,1959.65 2130.15,1959.41 2150.44,1959.41 R907.2@2152.15,1957.7
  Signal Layer 3 w3.94: v1(1754.92,2044.29) 1775.37,2044.29 1782.26,2037.4 2052.66,2037.4 v1(2128.94,1961.12)
  Signal Layer 4 w3.94: v1(1686.02,1781.5) 1743.11,1838.58 1743.11,2032.48 v1(1754.92,2044.29) ; v1(2080.15,1835.71) 2078.99,1835.71 2069.88,1844.81 2069.88,1902.06 v1(2128.94,1961.12)
BOARD_ID_SDA: R908.2 U900.J12 U901.5 U950.2 | length 917.3
  Top Layer w3.94: v1(1690.94,1816.93) 1706.69,1801.18 1726.38,1801.18 U900.J12@1736.22,1791.34 ; U901.5@2100.18,1937.01 2100.35,1936.83 2127.93,1936.83 2128.56,1936.2 2149.09,1936.2 R908.2@2149.55,1935.75 ; U950.2@2111.22,1802.56 2111.22,1812.02 2126.97,1827.77 2126.97,1848.43 v1(2126.75,1848.64)
  Signal Layer 3 w3.94: v1(1714.57,2026.57) 2038.19,2026.57 v1(2128.11,1936.66)
  Signal Layer 4 w3.94: v1(1690.94,1816.93) 1703.79,1829.78 1703.79,2014.85 1714.57,2025.63 v1(1714.57,2026.57) ; v1(2126.75,1848.64) 2128.11,1849.99 v1(2128.11,1936.66)
BOARD_ID_WP: R909.2 U900.F13 U901.7 | length 929.6
  Top Layer w3.94: v1(1627.95,1770.67) 1645.67,1770.67 1651.48,1764.86 1664.68,1764.46 1679.13,1750 1688.98,1750 1706.69,1732.28 U900.F13@1716.54,1732.28 ; U901.7@2100.18,1976.38 2104.12,1980.31 2119.67,1980.31 2124.42,1985.06 v1(2128.76,1985.06) ; v1@2128.76,1984.66 2133.51,1984.66 v1@2136.18,1981.99 ; v1@2132.87,1980.32 2134.54,1981.99 v1@2136.18,1981.99 ; R909.2@2152.59,1978.37 2139.8,1978.37 v1@2136.18,1981.99
  Signal Layer 3 w3.94: v1(1798.23,2057.09) 1799.71,2057.09 1808.57,2048.23 2065.6,2048.23 v1(2128.76,1985.06)
  Signal Layer 4 w3.94: v1(1627.95,1770.67) 1646.65,1770.67 1652.56,1764.76 1691.17,1764.76 1751.97,1825.57 1751.97,2010.83 v1(1798.23,2057.09)
BOARD_VER0: R930.1 U900.M5 | length 126
  Top Layer w3.94: U900.M5@1874.02,1850.39 1864.17,1860.24 1864.17,1876.97 1859.25,1881.89 1859.25,1949.94 1868.1,1958.8 1869.77,1958.8 R930.1@1874.1,1963.13
BOARD_VER1: R931.1 U900.M6 | length 150.4
  Top Layer w3.94: U900.M6@1854.33,1850.39 1844.49,1860.24 1844.49,1880.91 1851.38,1887.8 1851.38,1962.01 1873.62,1984.25 R931.1@1874.02,1984.25
DBG_VREGO: C902.1 U900.A12 | length 93.8
  Top Layer w3.94: C902.1@1675.2,1569.88 1677.17,1567.91 C902.1@1678.15,1567.91
  Top Layer w7.87: 1723.54,1621.18 U900.A12@1736.22,1633.86
  Top Layer w11.81: C902.1@1678.15,1567.91 1678.15,1575.79 1723.54,1621.18
DEBUG_#RESET_C2CKPS: C8.1 J103.3 Q800.6 R9.2 R307.1 SW1.1 SW1.2 TP154.1 | length 4510.5
  Top Layer w3.94: Q800.6@2689.96,1442.91 2691.93,1444.88 v1(2711.61,1444.88) ; R307.1@2990.16,292.32 2990.16,219.74 3018.5,191.39 3018.5,138.98 J103.3@3021.65,135.83 ; v1(4049.21,570.87) R9.2@4074.8,570.87 4075.79,571.85 C8.1@4098.43,571.85 4098.43,571.06 4102.76,566.73 4103.54,566.73 4112.54,557.73 4133.21,557.73 SW1.1@4136.81,554.13 SW1.2@4300.2,554.13
  Signal Layer 3 w3.94: v1(2711.61,1444.88) 2739.48,1444.88 2762.82,1421.54 2939.68,1421.54 2962.6,1398.62 2962.6,1279.53 3014.76,1227.36 3289.37,1227.36 3327.48,1265.47 3607.99,1265.47 3688.98,1346.46 v1(3981.3,1346.46) ; J103.3@3012.8,142.72 3018.5,148.43 3018.5,390.55 3300.2,672.24 3947.83,672.24 v1(4049.21,570.87)
  Signal Layer 4 w3.94: v1(3981.3,1346.46) 3981.41,1346.57 4218.39,1346.57 4243.11,1321.85 4243.11,814.73 4049.21,620.83 v1(4049.21,570.87)
  Bottom Layer w3.94: TP154.1@4011.81,570.87 v1(4049.21,570.87)
DEBUG_#RESET_IN: U808.7 U900.N5 | length 932
  Top Layer w3.94: U900.N5@1874.02,1870.08 1891.73,1887.8 1891.73,1895.67 1912.4,1916.34 1912.4,1948.82 v1(1934.06,1970.47) ; v1(2388.83,1688.38) 2390.5,1686.71 2423.72,1686.71 U808.7@2425.39,1685.04
  Signal Layer 4 w3.94: v1(1934.06,1970.47) 2001.97,1970.47 2087.6,2056.1 2218.5,2056.1 2358.27,1916.34 2358.27,1797.24 2401.57,1753.94 2401.57,1703.64 2388.83,1690.89 v1(2388.83,1688.38)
